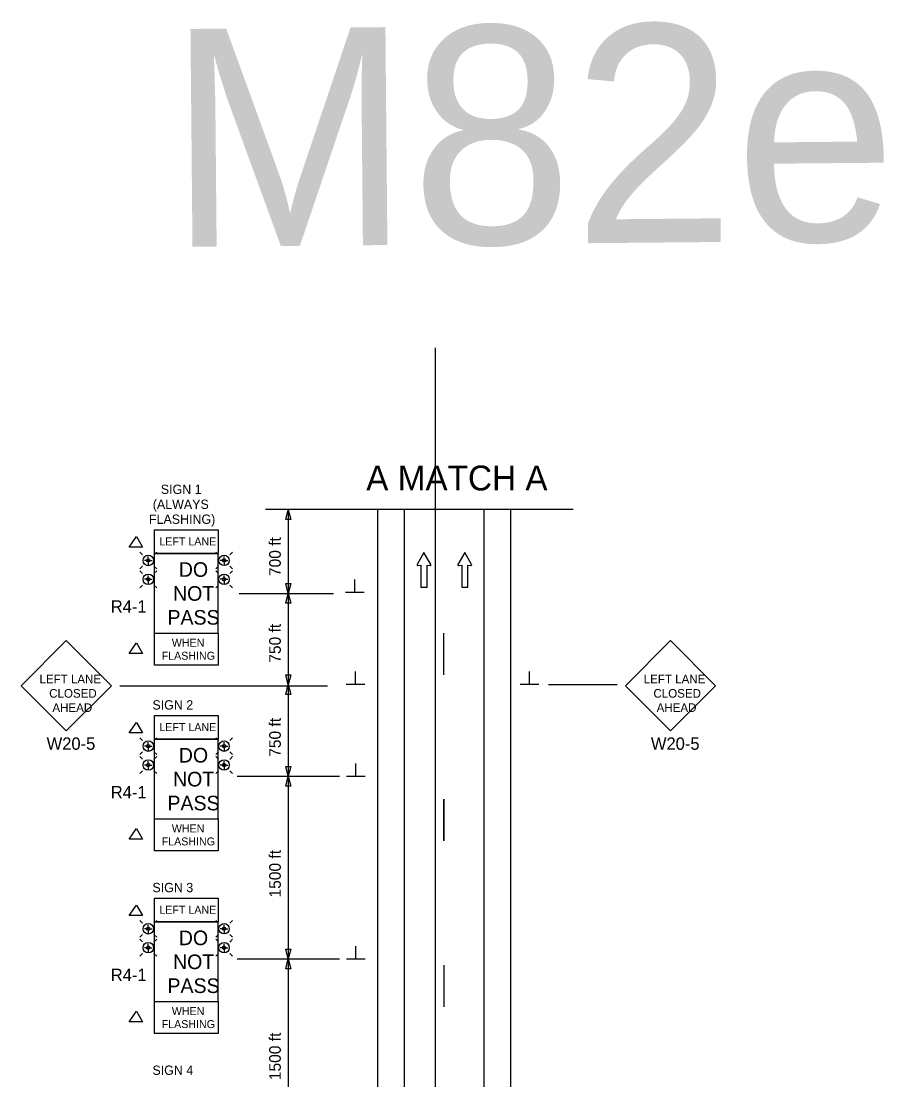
# Model space of a CAD drawing. Extents: x 15262 to 18126, y 1908 to 6555.
# Drawn here: x 16362 to 16881, y 2796 to 3433 of the extents above; entities that cross this region are included whole.
import ezdxf

# ---------------------------------------------------------------- set-up
doc = ezdxf.new("R2010")
doc.units = 0
for name, color, linetype in [('ALI_LEGAL_EX', 7, 'Continuous'), ('MT_SCRATCH_LEVEL_E', 7, 'Continuous'), ('PAVT_EDGE_EX', 7, 'Continuous'), ('TRAFFIC_SIGNS_PR', 7, 'Continuous'), ('TYPICAL_TEXT_DIMEN_PR', 7, 'Continuous')]:
    doc.layers.add(name, color=color, linetype=linetype)

msp = doc.modelspace()

# ---------------------------------------------------------------- linework, layer by layer
at = {"layer": 'ALI_LEGAL_EX'}
msp.add_line((16610.98, 3236.46), (16610.98, 2407.28), dxfattribs=at)
for points in [[(16616.07, 3064.67), (16616.07, 3039.67)], [(16616.07, 2964.67), (16616.07, 2939.67)], [(16616.35, 2964.74), (16616.35, 2939.74)], [(16616.35, 2864.74), (16616.35, 2839.74)]]:
    msp.add_lwpolyline(points, dxfattribs=at)
at = {"layer": 'MT_SCRATCH_LEVEL_E'}
for p, q in [((16604.32, 3113.3), (16600.21, 3106.06)), ((16608.47, 3106.06), (16604.32, 3113.3)), ((16628.88, 3113.3), (16624.77, 3106.06)), ((16633.03, 3106.06), (16628.88, 3113.3)), ((16600.69, 3105.38), (16602.47, 3105.69)), ((16602.47, 3105.69), (16602.47, 3092.43)), ((16606.21, 3092.43), (16606.21, 3105.69)), ((16606.21, 3105.69), (16607.99, 3105.38)), ((16625.25, 3105.38), (16627.03, 3105.69)), ((16627.03, 3105.69), (16627.03, 3092.43)), ((16630.77, 3092.43), (16630.77, 3105.69)), ((16630.77, 3105.69), (16632.55, 3105.38)), ((16602.47, 3092.43), (16606.21, 3092.43)), ((16627.03, 3092.43), (16630.77, 3092.43))]:
    msp.add_line(p, q, dxfattribs=at)
for centre, start, end in [((16600.62, 3105.84), 150.42484, 279.96381), ((16608.06, 3105.84), 260.03619, 29.77312), ((16625.17, 3105.84), 150.42484, 279.96381), ((16632.62, 3105.84), 260.03619, 29.77312)]:
    msp.add_arc(centre, 0.463, start, end, dxfattribs=at)
at = {"layer": 'PAVT_EDGE_EX'}
for p, q in [((16576.35, 3138.78), (16576.35, 2305.55)), ((16592.35, 3138.78), (16592.35, 2305.55)), ((16640.35, 3138.78), (16640.35, 2305.55)), ((16656.35, 3138.78), (16656.35, 2305.55))]:
    msp.add_line(p, q, dxfattribs=at)
at = {"layer": 'TRAFFIC_SIGNS_PR'}
for p, q in [((16434.9, 3111.91), (16433.27, 3113.53)), ((16441.74, 3111.91), (16443.37, 3113.53)), ((16442.06, 3064.61), (16442.06, 3112.61)), ((16442.06, 3112.61), (16480.46, 3112.61)), ((16480.54, 3111.92), (16478.91, 3113.55)), ((16480.46, 3064.61), (16480.46, 3112.61)), ((16487.39, 3111.92), (16489.02, 3113.55)), ((16434.9, 3105.06), (16433.27, 3103.43)), ((16438.32, 3108.48), (16436.02, 3108.48)), ((16438.32, 3108.48), (16438.32, 3110.78)), ((16438.32, 3108.48), (16438.32, 3105.33)), ((16438.32, 3108.48), (16440.62, 3108.48)), ((16443.37, 3103.43), (16441.74, 3105.06)), ((16480.54, 3105.07), (16478.91, 3103.45)), ((16483.96, 3108.5), (16481.66, 3108.5)), ((16483.96, 3108.5), (16483.96, 3110.8)), ((16483.96, 3108.5), (16483.96, 3105.35)), ((16483.96, 3108.5), (16486.27, 3108.5)), ((16489.01, 3103.45), (16487.39, 3105.07)), ((16434.9, 3100.53), (16433.27, 3102.16)), ((16438.32, 3097.11), (16438.32, 3099.41)), ((16441.74, 3100.53), (16443.37, 3102.16)), ((16480.54, 3100.53), (16478.91, 3102.16)), ((16483.96, 3097.11), (16483.96, 3099.41)), ((16487.39, 3100.53), (16489.02, 3102.16)), ((16434.9, 3093.68), (16433.27, 3092.06)), ((16438.32, 3097.11), (16436.02, 3097.11)), ((16438.32, 3097.11), (16438.32, 3093.96)), ((16438.32, 3097.11), (16440.62, 3097.11)), ((16443.37, 3092.06), (16441.74, 3093.68)), ((16480.54, 3093.68), (16478.91, 3092.06)), ((16483.96, 3097.11), (16481.66, 3097.11)), ((16483.96, 3097.11), (16483.96, 3093.96)), ((16483.96, 3097.11), (16486.27, 3097.11)), ((16489.01, 3092.06), (16487.39, 3093.68)), ((16388.92, 3060.19), (16361.77, 3033.04)), ((16416.08, 3033.04), (16388.92, 3060.19)), ((16442.06, 3064.61), (16480.46, 3064.61)), ((16752.78, 3060.19), (16725.62, 3033.04)), ((16779.93, 3033.04), (16752.78, 3060.19)), ((16361.77, 3033.04), (16388.92, 3005.88)), ((16388.92, 3005.88), (16416.08, 3033.04)), ((16725.62, 3033.04), (16752.78, 3005.88)), ((16752.78, 3005.88), (16779.93, 3033.04)), ((16434.9, 3000.08), (16433.27, 3001.71)), ((16438.32, 2996.66), (16436.02, 2996.66)), ((16438.32, 2996.66), (16438.32, 2998.96)), ((16438.32, 2996.66), (16438.32, 2993.51)), ((16438.32, 2996.66), (16440.62, 2996.66)), ((16441.74, 3000.08), (16443.37, 3001.71)), ((16442.06, 2952.78), (16442.06, 3000.78)), ((16442.06, 3000.78), (16480.46, 3000.78)), ((16480.54, 3000.1), (16478.91, 3001.72)), ((16480.46, 2952.78), (16480.46, 3000.78)), ((16483.96, 2996.67), (16481.66, 2996.67)), ((16483.96, 2996.67), (16483.96, 2998.97)), ((16483.96, 2996.67), (16483.96, 2993.52)), ((16483.96, 2996.67), (16486.27, 2996.67)), ((16487.39, 3000.1), (16489.02, 3001.72)), ((16434.9, 2993.23), (16433.27, 2991.6)), ((16434.9, 2988.71), (16433.27, 2990.33)), ((16443.37, 2991.6), (16441.74, 2993.23)), ((16441.74, 2988.7), (16443.37, 2990.33)), ((16480.54, 2993.25), (16478.91, 2991.62)), ((16480.54, 2988.71), (16478.91, 2990.33)), ((16489.01, 2991.62), (16487.39, 2993.25)), ((16487.39, 2988.7), (16489.02, 2990.33)), ((16438.32, 2985.28), (16436.02, 2985.28)), ((16438.32, 2985.28), (16438.32, 2987.58)), ((16438.32, 2985.28), (16438.32, 2982.13)), ((16438.32, 2985.28), (16440.62, 2985.28)), ((16483.96, 2985.28), (16481.66, 2985.28)), ((16483.96, 2985.28), (16483.96, 2987.58)), ((16483.96, 2985.28), (16483.96, 2982.13)), ((16483.96, 2985.28), (16486.27, 2985.28)), ((16434.9, 2981.86), (16433.27, 2980.23)), ((16443.37, 2980.23), (16441.74, 2981.86)), ((16480.54, 2981.86), (16478.91, 2980.23)), ((16489.01, 2980.23), (16487.39, 2981.86)), ((16442.06, 2952.78), (16480.46, 2952.78)), ((16434.9, 2890.08), (16433.27, 2891.71)), ((16438.32, 2886.66), (16438.32, 2888.96)), ((16441.74, 2890.08), (16443.37, 2891.71)), ((16442.06, 2842.78), (16442.06, 2890.78)), ((16442.06, 2890.78), (16480.46, 2890.78)), ((16480.54, 2890.1), (16478.91, 2891.72)), ((16480.46, 2842.78), (16480.46, 2890.78)), ((16483.96, 2886.67), (16483.96, 2888.97)), ((16487.39, 2890.1), (16489.02, 2891.72)), ((16434.9, 2883.23), (16433.27, 2881.6)), ((16438.32, 2886.66), (16436.02, 2886.66)), ((16438.32, 2886.66), (16438.32, 2883.51)), ((16438.32, 2886.66), (16440.62, 2886.66)), ((16443.37, 2881.6), (16441.74, 2883.23)), ((16480.54, 2883.25), (16478.91, 2881.62)), ((16483.96, 2886.67), (16481.66, 2886.67)), ((16483.96, 2886.67), (16483.96, 2883.52)), ((16483.96, 2886.67), (16486.27, 2886.67)), ((16489.01, 2881.62), (16487.39, 2883.25)), ((16434.9, 2878.71), (16433.27, 2880.33)), ((16438.32, 2875.28), (16436.02, 2875.28)), ((16438.32, 2875.28), (16438.32, 2877.58)), ((16438.32, 2875.28), (16438.32, 2872.13)), ((16438.32, 2875.28), (16440.62, 2875.28)), ((16441.74, 2878.7), (16443.37, 2880.33)), ((16480.54, 2878.71), (16478.91, 2880.33)), ((16483.96, 2875.28), (16481.66, 2875.28)), ((16483.96, 2875.28), (16483.96, 2877.58)), ((16483.96, 2875.28), (16483.96, 2872.13)), ((16483.96, 2875.28), (16486.27, 2875.28)), ((16487.39, 2878.7), (16489.02, 2880.33)), ((16434.9, 2871.86), (16433.27, 2870.23)), ((16443.37, 2870.23), (16441.74, 2871.86)), ((16480.54, 2871.86), (16478.91, 2870.23)), ((16489.01, 2870.23), (16487.39, 2871.86)), ((16442.06, 2842.78), (16480.46, 2842.78))]:
    msp.add_line(p, q, dxfattribs=at)
for centre, radius in [((16438.32, 3108.48), 3.15), ((16483.96, 3108.5), 3.15), ((16438.32, 3108.48), 1.02), ((16483.96, 3108.5), 1.02), ((16438.32, 3097.11), 3.15), ((16483.96, 3097.11), 3.15), ((16438.32, 3097.11), 1.02), ((16483.96, 3097.11), 1.02), ((16438.32, 2996.65), 3.15), ((16438.32, 2996.65), 1.02), ((16483.96, 2996.67), 3.15), ((16483.96, 2996.67), 1.02), ((16438.32, 2985.28), 3.15), ((16438.32, 2985.28), 1.02), ((16483.96, 2985.28), 3.15), ((16483.96, 2985.28), 1.02), ((16438.32, 2886.65), 3.15), ((16483.96, 2886.67), 3.15), ((16438.32, 2886.65), 1.02), ((16483.96, 2886.67), 1.02), ((16438.32, 2875.28), 3.15), ((16438.32, 2875.28), 1.02), ((16483.96, 2875.28), 3.15), ((16483.96, 2875.28), 1.02)]:
    msp.add_circle(centre, radius, dxfattribs=at)
at = {"layer": 'TYPICAL_TEXT_DIMEN_PR'}
for p, q in [((16508.93, 3139.37), (16694.24, 3139.37)), ((16521.05, 3133.07), (16522.62, 3138.93)), ((16522.62, 3138.93), (16524.19, 3133.07)), ((16522.62, 3138.65), (16522.62, 3068.65)), ((16522.62, 3133.07), (16521.05, 3133.07)), ((16524.19, 3133.07), (16522.62, 3133.07)), ((16522.62, 3088.64), (16521.05, 3094.51)), ((16521.05, 3094.51), (16522.62, 3094.51)), ((16522.62, 3094.51), (16524.19, 3094.51)), ((16524.19, 3094.51), (16522.62, 3088.64)), ((16562.78, 3089.31), (16562.78, 3097.09)), ((16492.95, 3088.64), (16549.74, 3088.64)), ((16521.05, 3082.78), (16522.62, 3088.64)), ((16522.62, 3088.64), (16522.62, 3018.64)), ((16522.62, 3088.64), (16524.19, 3082.78)), ((16557.15, 3089.31), (16568.4, 3089.31)), ((16522.62, 3082.78), (16521.05, 3082.78)), ((16524.19, 3082.78), (16522.62, 3082.78)), ((16563, 3033.88), (16563, 3041.66)), ((16667.92, 3033.77), (16667.92, 3041.56)), ((16522.62, 3033.66), (16521.06, 3039.53)), ((16521.06, 3039.53), (16522.62, 3039.53)), ((16522.62, 3039.53), (16524.19, 3039.53)), ((16524.19, 3039.53), (16522.62, 3033.66)), ((16421.18, 3032.92), (16546.13, 3032.92)), ((16521.05, 3027.82), (16522.62, 3033.68)), ((16522.62, 3033.68), (16524.19, 3027.82)), ((16522.62, 3033.48), (16522.62, 2963.48)), ((16557.38, 3033.88), (16568.62, 3033.88)), ((16673.55, 3033.77), (16662.3, 3033.77)), ((16720.72, 3033.52), (16679.35, 3033.52)), ((16522.62, 3027.82), (16521.05, 3027.82)), ((16524.19, 3027.82), (16522.62, 3027.82)), ((16522.62, 2978.48), (16521.06, 2984.34)), ((16521.06, 2984.34), (16522.62, 2984.34)), ((16522.62, 2988.35), (16522.62, 2984.58)), ((16522.62, 2984.34), (16524.19, 2984.34)), ((16524.19, 2984.34), (16522.62, 2978.48)), ((16563.23, 2978.48), (16563.23, 2986.26)), ((16491.89, 2978.48), (16553.35, 2978.48)), ((16521.06, 2972.61), (16522.62, 2978.48)), ((16522.62, 2978.48), (16522.62, 2868.48)), ((16522.62, 2978.48), (16524.19, 2972.61)), ((16557.6, 2978.48), (16568.85, 2978.48)), ((16522.62, 2972.61), (16521.06, 2972.61)), ((16524.19, 2972.61), (16522.62, 2972.61)), ((16563.23, 2868.48), (16563.23, 2876.26)), ((16522.62, 2868.48), (16521.06, 2874.34)), ((16521.06, 2874.34), (16522.62, 2874.34)), ((16522.62, 2874.34), (16524.19, 2874.34)), ((16524.19, 2874.34), (16522.62, 2868.48)), ((16491.89, 2868.48), (16553.35, 2868.48)), ((16521.06, 2862.61), (16522.62, 2868.48)), ((16522.62, 2862.61), (16521.06, 2862.61)), ((16522.62, 2868.48), (16522.62, 2758.48)), ((16522.62, 2868.48), (16524.19, 2862.61)), ((16524.19, 2862.61), (16522.62, 2862.61)), ((16557.6, 2868.48), (16568.85, 2868.48))]:
    msp.add_line(p, q, dxfattribs=at)
for points in [[(16442.06, 3127), (16480.46, 3127), (16480.46, 3112.61), (16442.06, 3112.61)], [(16426.76, 3116.5), (16431.12, 3122.8), (16434.83, 3116.5)], [(16442.06, 3064.61), (16480.46, 3064.61), (16480.46, 3045.41), (16442.06, 3045.41)], [(16426.76, 3052.53), (16431.12, 3058.83), (16434.83, 3052.53)], [(16426.76, 3004.67), (16431.12, 3010.97), (16434.83, 3004.67)], [(16442.06, 3015.18), (16480.46, 3015.18), (16480.46, 3000.78), (16442.06, 3000.78)], [(16442.06, 2952.78), (16480.46, 2952.78), (16480.46, 2933.59), (16442.06, 2933.59)], [(16426.76, 2940.7), (16431.12, 2947.01), (16434.83, 2940.7)], [(16426.76, 2894.67), (16431.12, 2900.97), (16434.83, 2894.67)], [(16442.06, 2905.18), (16480.46, 2905.18), (16480.46, 2890.78), (16442.06, 2890.78)], [(16442.06, 2842.78), (16480.46, 2842.78), (16480.46, 2823.59), (16442.06, 2823.59)], [(16426.76, 2830.7), (16431.12, 2837.01), (16434.83, 2830.7)]]:
    msp.add_lwpolyline(points, close=True, dxfattribs=at)

# ---------------------------------------------------------------- texts
at = {"layer": 'TRAFFIC_SIGNS_PR'}
for s, height, p in [('DO', 8.8, (16456.69, 3098.61)), ('NOT', 8.8, (16453.2, 3084.21)), ('R4-1', 7.44, (16415.74, 3077.03)), ('PASS', 8.8, (16449.85, 3069.81)), ('LEFT LANE', 5.2, (16372.8, 3034.43)), ('LEFT LANE', 5.2, (16736.66, 3034.43)), ('CLOSED', 5.2, (16378.64, 3025.83)), ('CLOSED', 5.2, (16742.49, 3025.83)), ('AHEAD', 5.2, (16380.58, 3017.23)), ('AHEAD', 5.2, (16744.43, 3017.23)), ('W20-5', 7.44, (16377.1, 2994.44)), ('W20-5', 7.44, (16740.95, 2994.44)), ('DO', 8.8, (16456.69, 2986.78)), ('NOT', 8.8, (16453.2, 2972.38)), ('R4-1', 7.44, (16415.74, 2965.2)), ('PASS', 8.8, (16449.85, 2957.98)), ('DO', 8.8, (16456.69, 2876.78)), ('NOT', 8.8, (16453.2, 2862.38)), ('R4-1', 7.44, (16415.74, 2855.2)), ('PASS', 8.8, (16449.85, 2847.98))]:
    msp.add_text(s, height=height, dxfattribs=at).set_placement(p)
at = {"layer": 'TYPICAL_TEXT_DIMEN_PR'}
for s, height, rotation, p in [('M82e', 131.22, 0.52295, (16450.52, 3297.22)), ('700 ft', 7, 90, (16518.1, 3099.07)), ('750 ft', 7, 90, (16518.1, 3046.88)), ('750 ft', 7, 90, (16518.1, 2990.23)), ('1500 ft', 7, 90, (16518.1, 2905.51)), ('1500 ft', 7, 90, (16518.1, 2795.51))]:
    msp.add_text(s, height=height, rotation=rotation, dxfattribs=at).set_placement(p)
for s, height, p in [('A MATCH A', 15, (16569.53, 3150.62)), (' SIGN 1 ', 5.6, (16443.76, 3148.51)), ('  (ALWAYS  ', 5.6, (16436.86, 3139.51)), ('  FLASHING) ', 5.6, (16434.55, 3130.51)), ('LEFT LANE', 4.8, (16444.98, 3117.51)), ('WHEN', 4.8, (16452.48, 3056.52)), ('FLASHING', 4.8, (16446.37, 3048.68)), ('   SIGN 2   ', 5.6, (16434.55, 3018.69)), ('LEFT LANE', 4.8, (16444.98, 3005.69)), ('WHEN', 4.8, (16452.48, 2944.69)), ('FLASHING', 4.8, (16446.37, 2936.86)), ('   SIGN 3   ', 5.6, (16434.56, 2908.69)), ('LEFT LANE', 4.8, (16444.98, 2895.69)), ('WHEN', 4.8, (16452.48, 2834.69)), ('FLASHING', 4.8, (16446.37, 2826.86)), ('   SIGN 4   ', 5.6, (16434.55, 2798.69))]:
    msp.add_text(s, height=height, dxfattribs=at).set_placement(p)

doc.saveas('drawing.dxf')
